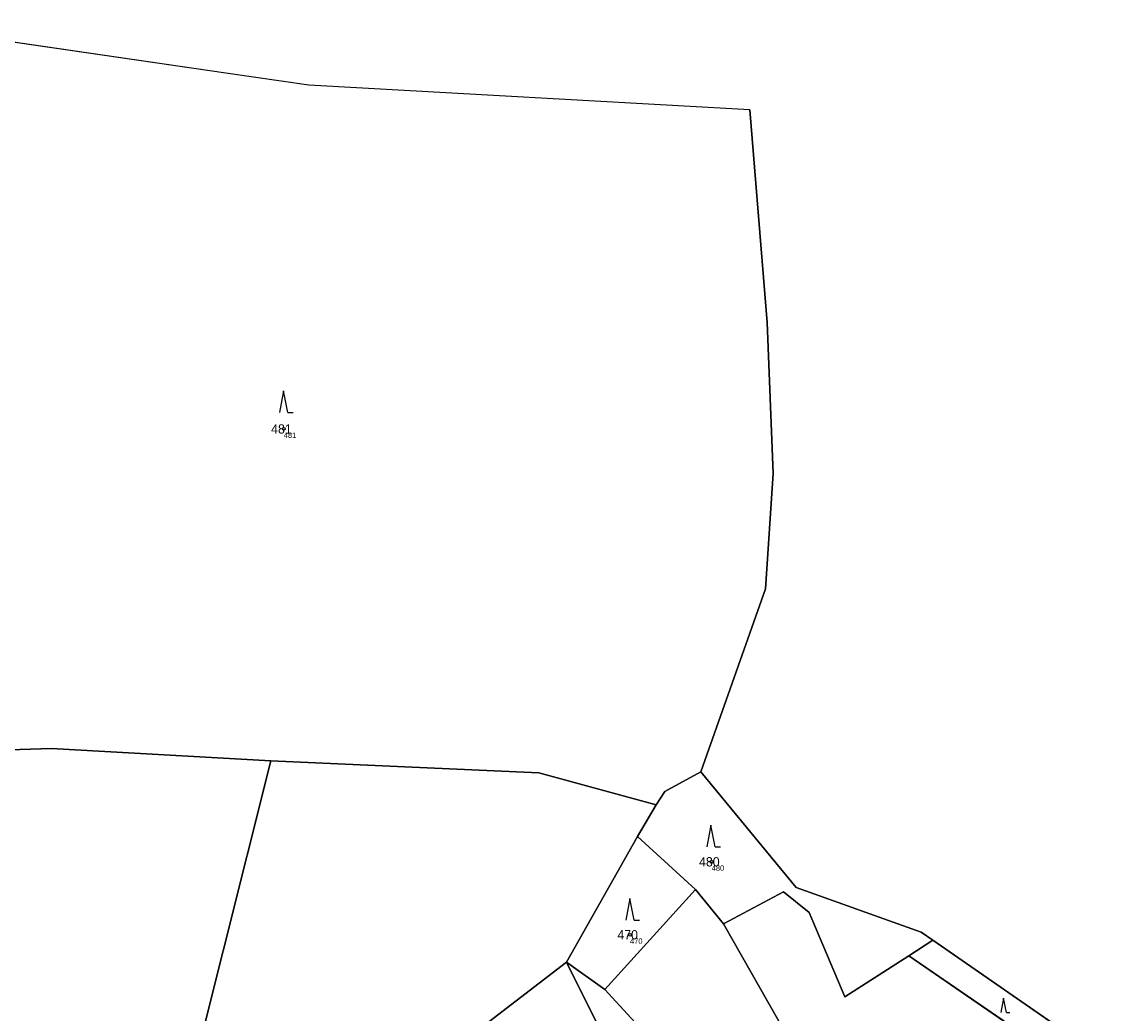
# Model space of a CAD drawing. Extents: x -554500 to -548272, y -1079733 to -1073730.
# Drawn here: x -551717.1 to -551514.4, y -1075521.8 to -1075339.3 of the extents above; entities that cross this region are included whole.
import ezdxf

# ---------------------------------------------------------------- set-up
doc = ezdxf.new("R2010")
doc.units = 0
for name, color, linetype in [('Definiční body', 7, 'Continuous'), ('Hranice parcel', 7, 'Continuous'), ('Parcelní čísla', 7, 'Continuous'), ('Polygon ku', 7, 'Continuous'), ('Polygon parcely', 7, 'Continuous'), ('Značky kultur', 7, 'Continuous')]:
    doc.layers.add(name, color=color, linetype=linetype)

msp = doc.modelspace()

# ---------------------------------------------------------------- linework, layer by layer
at = {"layer": 'Definiční body'}
for centre in [(-551668.96, -1075414.16994), (-551590.24, -1075493.81994), (-551605.27, -1075507.24994)]:
    msp.add_circle(centre, 0.25, dxfattribs=at)
at = {"layer": 'Hranice parcel'}
for p, q in [((-551679.6, -1075348.67), (-551744.1, -1075339.33)), ((-551664.36, -1075350.88), (-551679.6, -1075348.67)), ((-551583.24, -1075355.43), (-551664.36, -1075350.88)), ((-551583.24, -1075355.43), (-551580.02, -1075394.59)), ((-551580.35, -1075443.56), (-551592.21, -1075477.25)), ((-551600.43, -1075483.34), (-551603.86, -1075489.16)), ((-551603.86, -1075489.16), (-551616.94, -1075512.32)), ((-551593.22, -1075498.92), (-551603.86, -1075489.16)), ((-551609.92, -1075517.35), (-551593.22, -1075498.92)), ((-551588.07, -1075505.25), (-551593.22, -1075498.92)), ((-551551.73, -1075506.74), (-551549.56, -1075508.24)), ((-551549.56, -1075508.24), (-551554, -1075511.14)), ((-551549.56, -1075508.24), (-551514.4, -1075532.57)), ((-551554, -1075511.14), (-551518.28, -1075535.59)), ((-551616.94, -1075512.32), (-551649.75, -1075537.47)), ((-551609.92, -1075517.35), (-551616.94, -1075512.32)), ((-551609.99, -1075526.19), (-551616.94, -1075512.32))]:
    msp.add_line(p, q, dxfattribs=at)
for points in [[(-551580.02, -1075394.59), (-551578.96, -1075422.34), (-551580.35, -1075443.56)], [(-551833.2, -1075475.57), (-551775.59, -1075475.01), (-551711.68, -1075472.96), (-551671.35, -1075475.23)], [(-551908.78, -1075679.57), (-551845.13, -1075640.16), (-551774, -1075594.76), (-551761.67, -1075597.82), (-551707.78, -1075585.61), (-551688.86, -1075545.18), (-551671.35, -1075475.23)], [(-551671.35, -1075475.23), (-551622.04, -1075477.44), (-551600.43, -1075483.34)], [(-551592.21, -1075477.25), (-551598.84, -1075480.9), (-551600.43, -1075483.34)], [(-551592.21, -1075477.25), (-551574.68, -1075498.55), (-551551.73, -1075506.74)], [(-551554, -1075511.14), (-551565.72, -1075518.65), (-551572.3, -1075503.16), (-551577.03, -1075499.37), (-551588.07, -1075505.25)], [(-551557.39, -1075553.61), (-551576.36, -1075525.85), (-551588.07, -1075505.25)], [(-551586.49, -1075562.61), (-551592.14, -1075543.72), (-551600.22, -1075527.89), (-551609.92, -1075517.35)]]:
    msp.add_lwpolyline(points, dxfattribs=at)
at = {"layer": 'Polygon ku'}
msp.add_lwpolyline([(-551514.4, -1075532.57), (-551549.56, -1075508.24), (-551551.73, -1075506.74), (-551574.68, -1075498.55), (-551592.21, -1075477.25), (-551580.35, -1075443.56), (-551578.96, -1075422.34), (-551580.02, -1075394.59), (-551583.24, -1075355.43), (-551664.36, -1075350.88), (-551679.6, -1075348.67), (-551744.1, -1075339.33)], dxfattribs=at)
at = {"layer": 'Polygon parcely'}
for points in [[(-551744.1, -1075339.33), (-551749.28, -1075339.29), (-551754.97, -1075373.4), (-551760.24, -1075424.25), (-551802.61, -1075420.73), (-551833.2, -1075475.57), (-551775.59, -1075475.01), (-551711.68, -1075472.96), (-551671.35, -1075475.23), (-551622.04, -1075477.44), (-551600.43, -1075483.34), (-551598.84, -1075480.9), (-551592.21, -1075477.25), (-551580.35, -1075443.56), (-551578.96, -1075422.34), (-551580.02, -1075394.59), (-551583.24, -1075355.43), (-551664.36, -1075350.88), (-551679.6, -1075348.67)], [(-551688.86, -1075545.18), (-551671.35, -1075475.23), (-551711.68, -1075472.96), (-551775.59, -1075475.01), (-551833.2, -1075475.57), (-551851.45, -1075477.28), (-551968.45, -1075587.37), (-551843.32, -1075592.1), (-551965.67, -1075685.39), (-551908.78, -1075679.57), (-551845.13, -1075640.16), (-551774, -1075594.76), (-551761.67, -1075597.82), (-551707.78, -1075585.61)], [(-551908.78, -1075679.57), (-551762.84, -1075664.65), (-551729.75, -1075668.79), (-551720.31, -1075645.47), (-551712.09, -1075636.75), (-551699.35, -1075596.46), (-551669.74, -1075565.36), (-551659.13, -1075548.13), (-551649.75, -1075537.47), (-551616.94, -1075512.32), (-551603.86, -1075489.16), (-551600.43, -1075483.34), (-551622.04, -1075477.44), (-551671.35, -1075475.23), (-551688.86, -1075545.18), (-551707.78, -1075585.61), (-551761.67, -1075597.82), (-551774, -1075594.76), (-551845.13, -1075640.16)], [(-551600.43, -1075483.34), (-551603.86, -1075489.16), (-551593.22, -1075498.92), (-551588.07, -1075505.25), (-551577.03, -1075499.37), (-551572.3, -1075503.16), (-551565.72, -1075518.65), (-551554, -1075511.14), (-551549.56, -1075508.24), (-551551.73, -1075506.74), (-551574.68, -1075498.55), (-551592.21, -1075477.25), (-551598.84, -1075480.9)], [(-551603.86, -1075489.16), (-551616.94, -1075512.32), (-551609.92, -1075517.35), (-551593.22, -1075498.92)], [(-551557.39, -1075553.61), (-551576.36, -1075525.85), (-551588.07, -1075505.25), (-551593.22, -1075498.92), (-551609.92, -1075517.35), (-551600.22, -1075527.89), (-551592.14, -1075543.72), (-551586.49, -1075562.61), (-551584.08, -1075566.35)], [(-551577.03, -1075499.37), (-551588.07, -1075505.25), (-551576.36, -1075525.85), (-551557.39, -1075553.61), (-551518.28, -1075535.59), (-551554, -1075511.14), (-551565.72, -1075518.65), (-551572.3, -1075503.16)], [(-551549.56, -1075508.24), (-551554, -1075511.14), (-551518.28, -1075535.59), (-551514.4, -1075532.57)], [(-551619.02, -1075552.73), (-551620.47, -1075536.97), (-551609.99, -1075526.19), (-551616.94, -1075512.32), (-551649.75, -1075537.47), (-551634.33, -1075565.77), (-551596.07, -1075565.58)], [(-551586.49, -1075562.61), (-551592.14, -1075543.72), (-551600.22, -1075527.89), (-551609.92, -1075517.35), (-551616.94, -1075512.32), (-551609.99, -1075526.19)]]:
    msp.add_lwpolyline(points, close=True, dxfattribs=at)
at = {"layer": 'Značky kultur'}
for p, q in [((-551668.98, -1075407.13), (-551669.73, -1075411.13)), ((-551668.23, -1075411.13), (-551668.98, -1075407.13)), ((-551668.23, -1075411.13), (-551667.234, -1075411.13)), ((-551590.38, -1075487.05), (-551591.13, -1075491.05)), ((-551589.63, -1075491.05), (-551590.38, -1075487.05)), ((-551589.63, -1075491.05), (-551588.634, -1075491.05)), ((-551605.27, -1075500.56), (-551606.02, -1075504.56)), ((-551604.52, -1075504.56), (-551605.27, -1075500.56)), ((-551604.52, -1075504.56), (-551603.524, -1075504.56)), ((-551536.54, -1075518.89), (-551537.042, -1075521.57)), ((-551536.038, -1075521.57), (-551536.54, -1075518.89)), ((-551536.038, -1075521.57), (-551535.37, -1075521.57))]:
    msp.add_line(p, q, dxfattribs=at)

# ---------------------------------------------------------------- texts
at = {"layer": 'Definiční body'}
for s, p in [('481', (-551668.96, -1075415.826)), ('480', (-551590.24, -1075495.476)), ('470', (-551605.27, -1075508.906))]:
    msp.add_text(s, height=0.999996, dxfattribs=at).set_placement(p)
at = {"layer": 'Parcelní čísla'}
for s, p in [('481', (-551671.285, -1075415.02)), ('480', (-551592.565, -1075494.67)), ('470', (-551607.595, -1075508.1))]:
    msp.add_text(s, height=1.699998, dxfattribs=at).set_placement(p)

doc.saveas('drawing.dxf')
